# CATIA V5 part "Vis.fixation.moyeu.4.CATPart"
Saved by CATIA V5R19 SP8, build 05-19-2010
Part number: Vis.fixation.moyeu.4
Bounding box of the stored display mesh (mm): x -24 to -18, y -1.5 to 1.5, z -1.5 to 1.5
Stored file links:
  G:\EU_thinkMotion\CFAO_2010\MMS_groupe3\MMS_groupe3\jbonnamy\jbonnamy_cfao\Vis.fixation.moyeu.4.CATPart
  C:\Users\Micheline\Desktop\projet CFAO\Nouveau dossier\temp\Nouveau dossier\Vis.fixation.CATPart
  G:\EU_thinkMotion\CFAO_2010\MMS_groupe3\MMS_groupe3\jbonnamy\jbonnamy_cfao\jbonnamy_suspension.arriere.directionnelle.CATProduct
  G:\EU_thinkMotion\CFAO_2010\MMS_groupe3\MMS_groupe3\jbonnamy\jbonnamy_cfao\Vis.fixation.moyeu.3.CATPart
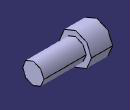
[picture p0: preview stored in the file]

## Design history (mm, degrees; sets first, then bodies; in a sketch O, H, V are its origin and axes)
External parameters (linked from other documents)
  External.Epaisseur.support.10 = 1.5 mm
  External.Diametre.vis.fixation = 2 mm
Set1
  DatumSurface1: linked copy from another document
Body1 (main body)
  Sketch1 on DatumSurface1, origin (-22, 0, 0), H (0, -1, 0), V (0, 0, 1)
    circle A1 centre (0, 0) radius 1
    radius A1 = 1 {= External.Diametre.vis.fixation /2}
  Pad1: profile Sketch1, direction (1, 0, 0), length 4 {= 2*External.Epaisseur.support.10 +1mm}
  Sketch2 on DatumSurface1, origin (-22, 0, 0), H (0, -1, 0), V (0, 0, 1)
    circle A1 centre (0, 0) radius 1.5
    radius A1 = 1.5 {= 3*External.Diametre.vis.fixation /4}
  Pad2: profile Sketch2, direction (-1, 0, 0), length 2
